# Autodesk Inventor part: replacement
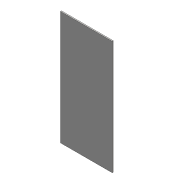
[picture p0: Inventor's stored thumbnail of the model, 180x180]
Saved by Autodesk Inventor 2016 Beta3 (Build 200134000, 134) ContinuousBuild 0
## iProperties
Created: 2016-03
Part Number: replacement
Material: Generic
Document SubType Name: Modeling
Designer: Gaurav
Density: 1 g/cm^3
Appearance: Default
Author: Gaurav
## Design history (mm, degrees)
sketch "Sketch1"
  geometry: L1 (125, 275)-(-125, 275); L2 (-125, 275)-(-125, -275); L3 (-125, -275)-(125, -275); L4 (125, -275)-(125, 275); L5 (125, 275)-(-125, -275); L6 (-125, 275)-(125, -275); 1 further point
  constraints: 12 end point, 2 midpoint, 2 parallel, 1 horizontal, 1 perpendicular
  dimensions: "d0" = 250 distance of L3.end L2.end; "d1" = 550 distance of L2.end L1.end
extrude "Extrusion1" new body sketch "Sketch1" distance "d2" = 5; taper "d3" = 0 deg
sketch "Sketch2"
  geometry: L1 (125, 275)-(-125, 275) reference; C1 r 6 at (0, 195); C2 r 6 at (0, -112); 1 further point
  constraints: 2 centre point
  dimensions: "d4" = 12 diameter of C1; "d5" = 80 distance from line of L1 C1.centre; "d6" = 12 diameter of C2; "d7" = 307 distance of C1.centre C2.centre
extrude "Extrusion2" join sketch "Sketch2" distance "d8" = 30; taper "d9" = 0 deg
body "Solid1"
